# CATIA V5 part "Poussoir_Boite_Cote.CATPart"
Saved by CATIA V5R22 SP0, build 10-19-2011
Part number: Poussoir_Boite_Cote
Bounding box of the stored display mesh (mm): x -5 to 0, y -80 to 80, z -17 to 17
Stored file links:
  D:\CAO_PER_MODIF_2025\CAO_PER_pick&place_2024P\Sous_Ensemble_Boite\Verin\Poussoir\Poussoir_Boite_Cote.CATPart
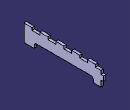
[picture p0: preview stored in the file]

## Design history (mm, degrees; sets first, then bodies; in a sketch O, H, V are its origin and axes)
Body1 (main body)
  Sketch1 on yz-plane, origin (0, 0, 0), H (0, 1, 0), V (0, 0, 1)
    line L1 (80, -17) -> (60, -17)
    line L2 (-80, -17) -> (-80, 17)
    line L3 (-80, 17) -> (80, 17)
    line L4 (80, 17) -> (80, -17)
    point P5 (-60, -17)
    line L5 (60, -17) -> (60, -12)
    line L6 (55, -7) -> (-55, -7)
    line L7 (-60, -12) -> (-60, -17)
    point P6 (60, -17)
    point P7 (60, -7)
    line L8 (-60, -17) -> (-80, -17)
    arc A1 centre (-55, -12) radius 5 from (-60, -12) to (-55, -7) cw
    arc A2 centre (55, -12) radius 5 from (55, -7) to (60, -12) cw
    length L3 = 160
    length L4 = 34
    distance L5 L4 = 20
    radius A1 = 5
    distance P6 P7 = 10
    radius A2 = 5
    horizontal: L1 H, L3 H, L6 H, L8 H
    vertical: L2 V, L4 V, L5 V, L7 V
    equidistance: L1 L3 O, L4 L2 O, L5 L7 O
    coincidence: P5 L1, L1 L8, L6 P7, L5 P7
    tangency: A1 L7, A1 L6, A2 L6, A2 L5
  Pad1: profile Sketch1, direction (-1, 0, 0), length 5
  Sketch2 on start face of Pad1, origin (0, 0, 0), H (0, 1, 0), V (0, 0, 1)
    point P1 (80, -5)
    line L1 (80, -5) -> (75, -5)
    line L2 (75, -5) -> (75, -17)
    line L3 (75, -17) -> (80, -17)
    line L4 (80, -17) -> (80, -5)
    point P2 (75, -5)
    point P3 (75, -17)
    point P4 (80, -17)
    reference projected line E1 (80, -17) -> (80, 17) from edge [face of Pad1 from Sketch1.L4 | start face of Pad1]
    reference projected line E2 (60, -17) -> (80, -17) from edge [face of Pad1 from Sketch1.L1 | start face of Pad1]
    point P5 (80, 5)
    point P6 (75, 5)
    point P7 (75, 17)
    point P8 (80, 17)
    line L5 (80, 5) -> (75, 5)
    line L6 (75, 5) -> (75, 17)
    line L7 (75, 17) -> (80, 17)
    line L8 (80, 17) -> (80, 5)
    length L3 = 5
    distance L5 L1 = 10
    horizontal: L1 H, L3 H
    vertical: L2 V, L4 V
    coincidence: L4 E1, L3 E2
    symmetry: P1 P5 H, P2 P6 H, P3 P7 H, P4 P8 H, L1 L5 H, L2 L6 H, L3 L7 H, L4 L8 H
  Pocket1: profile Sketch2, direction (-1, 0, 0), through (limit type 6)
  Sketch3 on start face of Pad1, origin (0, 0, 0), H (0, 1, 0), V (0, 0, 1)
    line L1 (64, 17) -> (80, 17)
    line L2 (80, 17) -> (80, 12)
    line L3 (80, 12) -> (64, 12)
    line L4 (64, 12) -> (64, 17)
    reference projected line E1 (80, -17) -> (80, 17) from edge [face of Pad1 from Sketch1.L4 | start face of Pad1]
    reference projected line E2 (80, 17) -> (-80, 17) from edge [face of Pad1 from Sketch1.L3 | start face of Pad1]
    point P5 (48, 17)
    line L5 (48, 17) -> (32, 17)
    line L6 (32, 17) -> (32, 12)
    line L7 (32, 12) -> (48, 12)
    line L8 (48, 12) -> (48, 17)
    point P7 (32, 12)
    point P9 (16, 17)
    line L9 (16, 17) -> (0, 17)
    line L10 (0, 17) -> (0, 12)
    line L11 (0, 12) -> (16, 12)
    line L12 (16, 12) -> (16, 17)
    point P11 (0, 12)
    point P13 (-16, 17)
    line L13 (-16, 17) -> (-32, 17)
    line L14 (-32, 12) -> (-16, 12)
    line L15 (-32, 17) -> (-32, 12)
    line L16 (-16, 12) -> (-16, 17)
    point P14 (-32, 12)
    point P17 (-48, 17)
    line L17 (-48, 17) -> (-64, 17)
    line L18 (-64, 12) -> (-48, 12)
    line L19 (-64, 17) -> (-64, 12)
    line L20 (-48, 12) -> (-48, 17)
    point P18 (-64, 12)
    length L2 = 5
    length L1 = 16
    distance L4 L8 = 16
    length L5 = 16
    distance L12 L6 = 16
    length L9 = 16
    length L13 = 16
    length L17 = 16
    distance L10 L16 = 16
    distance L20 L15 = 16
    horizontal: L1 H, L3 H, L5 H, L7 H, L9 H, L11 H, L13 H, L14 H, L17 H, L18 H
    vertical: L2 V, L4 V, L6 V, L8 V, L10 V, L12 V, L15 V, L16 V, L19 V, L20 V
    coincidence: L2 E1, L1 E2, P5 L1, P7 L3, P9 L1, P11 L3, P13 L1, P14 L3, P17 L1, P18 L3
  Pocket2: profile Sketch3, direction (-1, 0, 0), through (limit type 6)
  Sketch4 on start face of Pad1, origin (0, 0, 0), H (0, 1, 0), V (0, 0, 1)
    line L1 (80, -17) -> (60, -17)
    line L2 (-80, -17) -> (-80, 17)
    line L3 (-80, 17) -> (80, 17)
    line L4 (80, 17) -> (80, -17)
    point P5 (-60, -17)
    line L5 (60, -17) -> (60, -12)
    line L6 (55, -7) -> (-55, -7)
    line L7 (-60, -12) -> (-60, -17)
    point P6 (60, -17)
    point P7 (60, -7)
    line L8 (-60, -17) -> (-80, -17)
    arc A1 centre (-55, -12) radius 5 from (-60, -12) to (-55, -7) cw
    arc A2 centre (55, -12) radius 5 from (55, -7) to (60, -12) cw
    length L3 = 160
    length L4 = 34
    distance L5 L4 = 20
    radius A1 = 5
    distance P6 P7 = 10
    radius A2 = 5
    horizontal: L1 H, L3 H, L6 H, L8 H
    vertical: L2 V, L4 V, L5 V, L7 V
    equidistance: L1 L3 O, L4 L2 O, L5 L7 O
    coincidence: P5 L1, L1 L8, L6 P7, L5 P7
    tangency: A1 L7, A1 L6, A2 L6, A2 L5
  Pad2: profile Sketch4, direction (-1, 0, 0), length 5
Current feature: Pocket2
